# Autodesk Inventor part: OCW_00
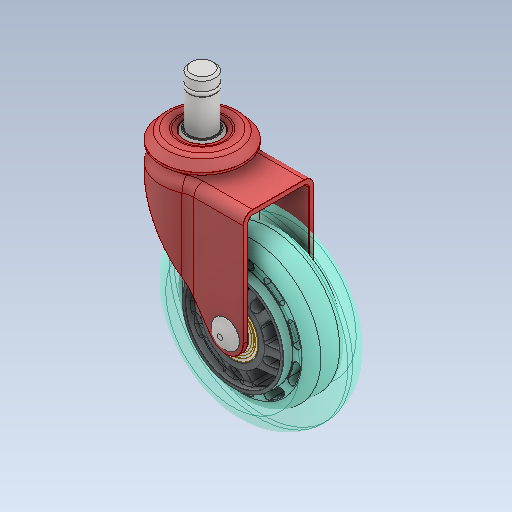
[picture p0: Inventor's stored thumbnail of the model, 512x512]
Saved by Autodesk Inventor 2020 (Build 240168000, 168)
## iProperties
Created: 2021-07
Part Number: OCW_00
Material: Ocel
Document SubType Name: Modeling
Designer: doma
Density: 7.85 g/cm^3
Appearance: Plech
Sending System: Autodesk Inventor 2020
Preprocessor: ST-DEVELOPER v18.1
Title: D:\Inventor projekty\Office chair wheels\OCW_00.stp
Author: MK
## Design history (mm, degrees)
feature "OCW_01_1:1"
feature "OCW_02_1:1"
feature "SKF_608-2Z_PART1_1:1"
feature "SKF_608-2Z_PART2_1:1"
feature "SKF_608-2Z_PART3_1:1"
feature "SKF_608-2Z_PART3_2:1"
feature "SKF_608-2Z_PART3_3:1"
feature "SKF_608-2Z_PART3_4:1"
feature "SKF_608-2Z_PART3_5:1"
feature "SKF_608-2Z_PART3_6:1"
feature "SKF_608-2Z_PART3_7:1"
feature "SKF_608-2Z_PART1_1:2"
feature "SKF_608-2Z_PART2_1:2"
feature "SKF_608-2Z_PART3_1:2"
feature "SKF_608-2Z_PART3_2:2"
feature "SKF_608-2Z_PART3_3:2"
feature "SKF_608-2Z_PART3_4:2"
feature "SKF_608-2Z_PART3_5:2"
feature "SKF_608-2Z_PART3_6:2"
feature "SKF_608-2Z_PART3_7:2"
feature "OCW_03_1:1"
feature "OCW_05_1:1"
feature "OCW_04_1:1"
feature "OCW_04_2:1"
feature "OCW_04_3:1"
feature "OCW_04_4:1"
feature "OCW_04_5:1"
feature "OCW_04_6:1"
feature "OCW_04_7:1"
feature "OCW_04_8:1"
feature "OCW_04_9:1"
feature "OCW_04_10:1"
feature "OCW_04_11:1"
feature "OCW_04_12:1"
feature "OCW_04_13:1"
feature "OCW_04_14:1"
feature "OCW_06_1:1"
feature "OCW_07_1:1"
feature "OCW_08_1:1"
feature "OCW_09_1:1"
feature "OCW_10_1:1"
feature "OCW_10_2:1"
feature "OCW_11_1:1"
node "Těleso1"
node "Těleso2"
node "Těleso3"
node "Těleso4"
node "Těleso5"
node "Těleso6"
node "Těleso7"
node "Těleso8"
node "Těleso9"
node "Těleso10"
node "Těleso11"
node "Těleso12"
node "Těleso13"
node "Těleso14"
node "Těleso15"
node "Těleso16"
node "Těleso17"
node "Těleso18"
node "Těleso19"
node "Těleso20"
node "Těleso21"
node "Těleso22"
node "Těleso23"
node "Těleso24"
node "Těleso25"
node "Těleso26"
node "Těleso27"
node "Těleso28"
node "Těleso29"
node "Těleso30"
node "Těleso31"
node "Těleso32"
node "Těleso33"
node "Těleso34"
node "Těleso35"
node "Těleso36"
node "Těleso37"
node "Těleso38"
node "Těleso39"
node "Těleso40"
node "Těleso41"
node "Těleso42"
node "Těleso43"
